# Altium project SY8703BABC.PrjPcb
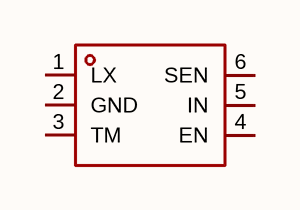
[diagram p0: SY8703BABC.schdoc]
1 sheet, 1 parts. Net scope: global (net labels, ports and power ports of the same name join across sheets).

## Sheet SY8703BABC.schdoc
size 127 x 101 mm

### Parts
U?  sy8703babc  [SOT-23-6_L2.9-W1.6-P0.95-LS2.8-BL]  (value not drawn)

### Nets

Not connected (* = marked no-connect by the designer): U? 1(LX) 2(GND) 3(TM) 4(EN) 5(IN) 6(SEN)

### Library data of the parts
U? = sy8703babc: 类型:-;工作电压(DC):2.5V~30V;开关频率:800kHz~1.2MHz;通道数:1;输出电压:-;输出电流:1A;调光:PWM;拓扑结构:降压;; Manufacturer: Silergy(矽力杰); AddInBom: yes; ModelId: 18da8f6c14a34920b3e136b5c401a119; ModelName: SOT-23-6_L2.9-W1.6-H1.5-LS2.8-P0.95; ModelTransform: 110.236,113.364,0,90,0,0,0.0005,0.0005,0; Number of Channels: 1; Output Current: 1A; Dimming: PWM; Topology: 降压; Switch Tube (Built-In/External): 内置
